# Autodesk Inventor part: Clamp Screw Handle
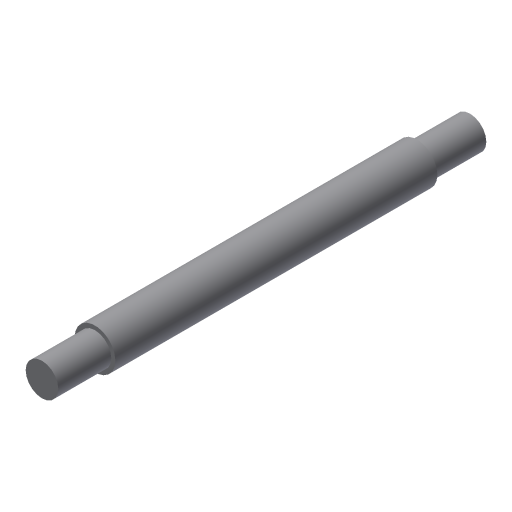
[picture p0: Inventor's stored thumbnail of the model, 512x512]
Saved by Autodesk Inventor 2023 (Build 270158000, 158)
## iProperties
Shininess: 77.0
Length Units: 11269
Angle Units: 11279
Time Units: 11290
Mass Units: 11283
Length Display Precision: 3
Angle Display Precision: 2
Compacted: True
Created: 2002-02
Part Number: Clamp Screw Handle
Document SubType Name: Modeling
Designer: ***
Density: 1 g/cm^3
Material: Generic
Appearance: Default
Density: 0.0
Volumn: 0.0
Area: 0.0
PropertySet Name: Model Information
Control State: 0
Master: False
Checked Out: False
Author: ***
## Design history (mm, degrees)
sketch "Sketch1"
  geometry: L1 (0, 105)-(4, 105); L2 (4, 105)-(4, 92); L3 (4, 92)-(5, 92); L4 (5, 92)-(5, 13); L5 (5, 13)-(4, 13); L6 (4, 13)-(4, 0); L7 (4, 0)-(0, 0); L8 (0, 0)-(0, 105)
  constraints: 16 end point, 5 parallel, 2 equal length, 1 collinear, 1 horizontal, 1 perpendicular
  dimensions: "d0" = 10 diameter of L4 L8; "d1" = 8 diameter of L2 L8; "d2" = 13 distance of L1.end L2.end; "d3" = 79 distance of L3.end L4.end
revolve "Revolution1" sketch "Sketch1" stored, may be unused: angle "d4" = 90 deg
body "Solid1"
